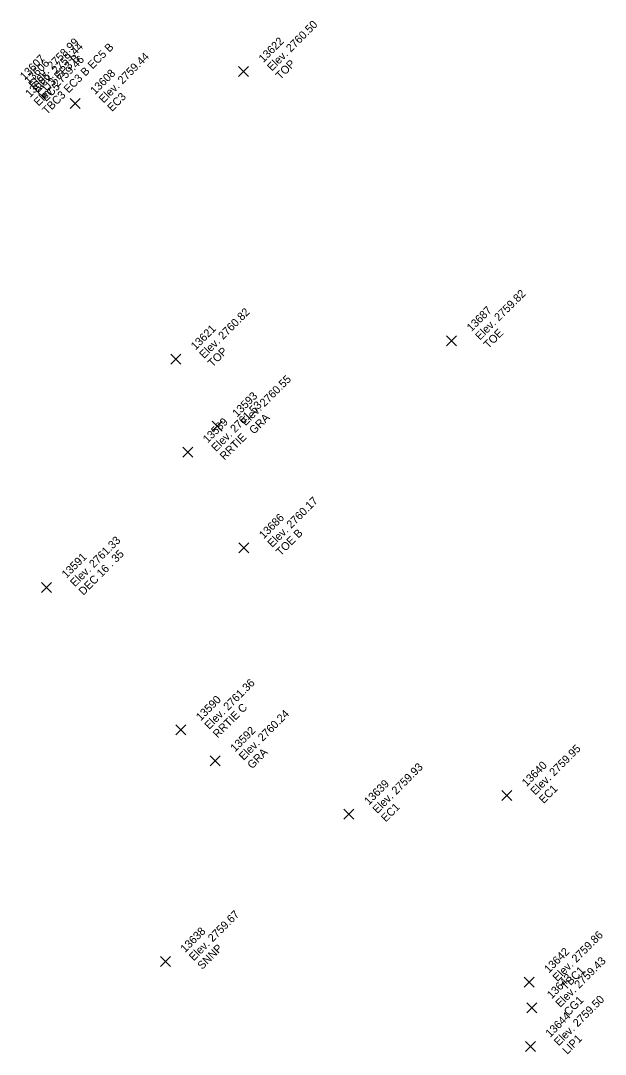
# Model space of a CAD drawing. Extents: x 2493999 to 2503109, y 700767 to 706646.
# Drawn here: x 2502220.48 to 2502238, y 702680.24 to 702711.23 of the extents above; entities that cross this region are included whole.
import ezdxf

# ---------------------------------------------------------------- set-up
doc = ezdxf.new("R2010")
doc.units = 0
doc.layers.add('ALG_CL_BLUE_Horiz', color=7, linetype='Continuous')
doc.layers.add('DES_SURFACE_Existing-Ground', color=7, linetype='Continuous')

msp = doc.modelspace()

# ---------------------------------------------------------------- linework, layer by layer
at = {"layer": 'ALG_CL_BLUE_Horiz'}
for points in [[(2502227.159, 702709.704), (2502227.009, 702709.854), (2502227.159, 702709.704), (2502227.009, 702709.554), (2502227.159, 702709.704), (2502227.309, 702709.554), (2502227.159, 702709.704), (2502227.309, 702709.854)], [(2502222.112, 702708.743), (2502221.962, 702708.893), (2502222.112, 702708.743), (2502221.962, 702708.593), (2502222.112, 702708.743), (2502222.262, 702708.593), (2502222.112, 702708.743), (2502222.262, 702708.893)], [(2502233.396, 702701.635), (2502233.246, 702701.785), (2502233.396, 702701.635), (2502233.246, 702701.485), (2502233.396, 702701.635), (2502233.546, 702701.485), (2502233.396, 702701.635), (2502233.546, 702701.785)], [(2502225.127, 702701.083), (2502224.977, 702701.233), (2502225.127, 702701.083), (2502224.977, 702700.933), (2502225.127, 702701.083), (2502225.277, 702700.933), (2502225.127, 702701.083), (2502225.277, 702701.233)], [(2502226.369, 702699.07), (2502226.219, 702699.22), (2502226.369, 702699.07), (2502226.219, 702698.92), (2502226.369, 702699.07), (2502226.519, 702698.92), (2502226.369, 702699.07), (2502226.519, 702699.22)], [(2502225.486, 702698.292), (2502225.336, 702698.442), (2502225.486, 702698.292), (2502225.336, 702698.142), (2502225.486, 702698.292), (2502225.636, 702698.142), (2502225.486, 702698.292), (2502225.636, 702698.442)], [(2502227.17, 702695.421), (2502227.02, 702695.571), (2502227.17, 702695.421), (2502227.02, 702695.271), (2502227.17, 702695.421), (2502227.32, 702695.271), (2502227.17, 702695.421), (2502227.32, 702695.571)], [(2502221.255, 702694.24), (2502221.105, 702694.39), (2502221.255, 702694.24), (2502221.105, 702694.09), (2502221.255, 702694.24), (2502221.405, 702694.09), (2502221.255, 702694.24), (2502221.405, 702694.39)], [(2502225.279, 702689.965), (2502225.129, 702690.115), (2502225.279, 702689.965), (2502225.129, 702689.815), (2502225.279, 702689.965), (2502225.429, 702689.815), (2502225.279, 702689.965), (2502225.429, 702690.115)], [(2502226.312, 702689.037), (2502226.162, 702689.187), (2502226.312, 702689.037), (2502226.162, 702688.887), (2502226.312, 702689.037), (2502226.462, 702688.887), (2502226.312, 702689.037), (2502226.462, 702689.187)], [(2502235.049, 702687.995), (2502234.899, 702688.145), (2502235.049, 702687.995), (2502234.899, 702687.845), (2502235.049, 702687.995), (2502235.199, 702687.845), (2502235.049, 702687.995), (2502235.199, 702688.145)], [(2502230.319, 702687.444), (2502230.169, 702687.594), (2502230.319, 702687.444), (2502230.169, 702687.294), (2502230.319, 702687.444), (2502230.469, 702687.294), (2502230.319, 702687.444), (2502230.469, 702687.594)], [(2502224.815, 702683.022), (2502224.665, 702683.172), (2502224.815, 702683.022), (2502224.665, 702682.872), (2502224.815, 702683.022), (2502224.965, 702682.872), (2502224.815, 702683.022), (2502224.965, 702683.172)], [(2502235.716, 702682.407), (2502235.566, 702682.557), (2502235.716, 702682.407), (2502235.566, 702682.257), (2502235.716, 702682.407), (2502235.866, 702682.257), (2502235.716, 702682.407), (2502235.866, 702682.557)], [(2502235.799, 702681.631), (2502235.649, 702681.781), (2502235.799, 702681.631), (2502235.649, 702681.481), (2502235.799, 702681.631), (2502235.949, 702681.481), (2502235.799, 702681.631), (2502235.949, 702681.781)], [(2502235.755, 702680.476), (2502235.605, 702680.626), (2502235.755, 702680.476), (2502235.605, 702680.326), (2502235.755, 702680.476), (2502235.905, 702680.326), (2502235.755, 702680.476), (2502235.905, 702680.626)]]:
    msp.add_lwpolyline(points, dxfattribs=at)

# ---------------------------------------------------------------- texts
at = {"layer": 'DES_SURFACE_Existing-Ground'}
for s, p in [('Elev. 2760.50', (2502228.008, 702709.704)), ('Elev. 2758.99', (2502220.854, 702709.178)), ('Elev. 2759.44', (2502220.982, 702709.044)), ('TBC3 EC3 B EC5 B', (2502221.267, 702708.399)), ('13622', (2502227.753, 702709.959)), ('13607', (2502220.599, 702709.433)), ('CU3 EP3 B', (2502221.108, 702708.923)), ('Elev. 2759.44', (2502222.961, 702708.743)), ('13606', (2502220.727, 702709.299)), ('Elev. 2759.46', (2502221.013, 702708.654)), ('TOP', (2502228.262, 702709.449)), ('13605', (2502220.758, 702708.909)), ('13608', (2502222.706, 702708.998)), ('EC5', (2502221.236, 702708.789)), ('EC3', (2502223.215, 702708.488)), ('Elev. 2759.82', (2502234.245, 702701.635)), ('Elev. 2760.82', (2502225.976, 702701.083)), ('13687', (2502233.99, 702701.89)), ('13621', (2502225.721, 702701.338)), ('TOE', (2502234.499, 702701.38)), ('TOP', (2502226.23, 702700.828)), ('Elev. 2760.55', (2502227.218, 702699.07)), ('13593', (2502226.963, 702699.325)), ('Elev. 2761.53', (2502226.335, 702698.292)), ('GRA', (2502227.472, 702698.815)), ('13589', (2502226.08, 702698.547)), ('RRTIE', (2502226.589, 702698.037)), ('Elev. 2760.17', (2502228.019, 702695.421)), ('13686', (2502227.764, 702695.676)), ('TOE B', (2502228.273, 702695.166)), ('Elev. 2761.33', (2502222.104, 702694.24)), ('DEC 16 . 35', (2502222.358, 702693.985)), ('13591', (2502221.849, 702694.495)), ('Elev. 2761.36', (2502226.128, 702689.965)), ('13590', (2502225.873, 702690.22)), ('RRTIE C', (2502226.382, 702689.71)), ('Elev. 2760.24', (2502227.161, 702689.037)), ('13592', (2502226.906, 702689.292)), ('Elev. 2759.95', (2502235.898, 702687.995)), ('GRA', (2502227.415, 702688.782)), ('Elev. 2759.93', (2502231.168, 702687.444)), ('13640', (2502235.643, 702688.25)), ('13639', (2502230.913, 702687.699)), ('EC1', (2502236.152, 702687.74)), ('EC1', (2502231.422, 702687.189)), ('Elev. 2759.67', (2502225.664, 702683.022)), ('13638', (2502225.409, 702683.277)), ('Elev. 2759.86', (2502236.565, 702682.407)), ('SNNP', (2502225.918, 702682.767)), ('13642', (2502236.31, 702682.662)), ('Elev. 2759.43', (2502236.648, 702681.631)), ('13643', (2502236.393, 702681.886)), ('TBC1', (2502236.819, 702682.152)), ('Elev. 2759.50', (2502236.604, 702680.476)), ('CG1', (2502236.902, 702681.376)), ('13644', (2502236.349, 702680.731)), ('LIP1', (2502236.858, 702680.221))]:
    msp.add_text(s, height=0.24, rotation=45, dxfattribs=at).set_placement(p)

doc.saveas('drawing.dxf')
